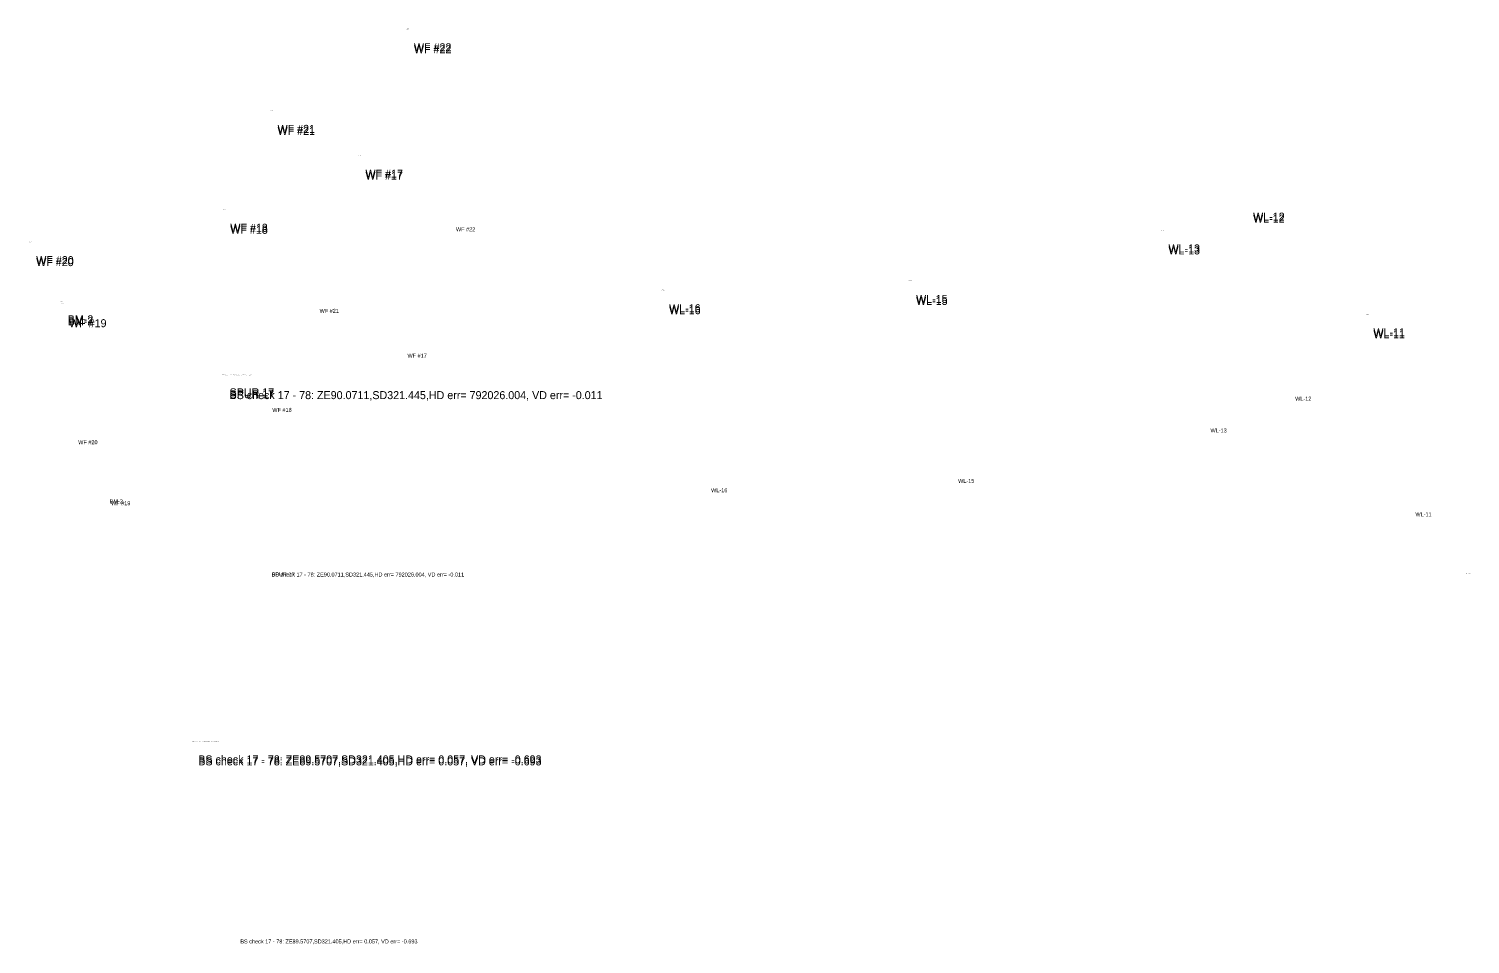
# Model space of a CAD drawing. Extents: x 5447 to 709667, y 4528 to 375472.
# Drawn here: x 705447 to 706023, y 375015 to 375381 of the extents above; entities that cross this region are included whole.
import ezdxf

# ---------------------------------------------------------------- set-up
doc = ezdxf.new("R2010")
doc.units = 0
doc.layers.add('SV_SURVEY_NOTES', color=7, linetype='Continuous')

msp = doc.modelspace()

# ---------------------------------------------------------------- texts
at = {"layer": 'SV_SURVEY_NOTES'}
for s, height, p in [('WF #22', 0.25, (705598.02, 375380.99)), ('WF #22', 3.2, (705600.97, 375372.26)), ('WF #22', 3.2, (705600.97, 375372.26)), ('WF #22', 3.2, (705600.97, 375372.26)), ('WF #22', 3.2, (705600.97, 375372.26)), ('WF #22', 3.2, (705600.97, 375372.26)), ('WF #22', 3.2, (705600.97, 375372.26)), ('WF #22', 3.2, (705600.97, 375372.26)), ('WF #22', 3.2, (705600.97, 375372.26)), ('WF #22', 3.2, (705600.97, 375371.46)), ('WF #22', 3.2, (705600.97, 375371.46)), ('WF #22', 3.2, (705600.97, 375371.46)), ('WF #21', 0.25, (705543.49, 375348.36)), ('WF #21', 3.2, (705546.44, 375339.63)), ('WF #21', 3.2, (705546.44, 375339.63)), ('WF #21', 3.2, (705546.44, 375339.63)), ('WF #21', 3.2, (705546.44, 375339.63)), ('WF #21', 3.2, (705546.44, 375339.63)), ('WF #21', 3.2, (705546.44, 375339.63)), ('WF #21', 3.2, (705546.44, 375339.63)), ('WF #21', 3.2, (705546.44, 375339.63)), ('WF #21', 3.2, (705546.44, 375338.83)), ('WF #21', 3.2, (705546.44, 375338.83)), ('WF #21', 3.2, (705546.44, 375338.83)), ('WF #17', 0.25, (705578.64, 375330.44)), ('WF #17', 3.2, (705581.59, 375321.71)), ('WF #17', 3.2, (705581.59, 375321.71)), ('WF #17', 3.2, (705581.59, 375321.71)), ('WF #17', 3.2, (705581.59, 375321.71)), ('WF #17', 3.2, (705581.59, 375321.71)), ('WF #17', 3.2, (705581.59, 375321.71)), ('WF #17', 3.2, (705581.59, 375321.71)), ('WF #17', 3.2, (705581.59, 375321.71)), ('WF #17', 3.2, (705581.59, 375320.91)), ('WF #17', 3.2, (705581.59, 375320.91)), ('WF #17', 3.2, (705581.59, 375320.91)), ('WL-12', 0.25, (705933.6, 375313.26)), ('WF #18', 0.25, (705524.6, 375308.78)), ('WL-12', 3.2, (705936.55, 375304.53)), ('WL-12', 3.2, (705936.55, 375304.53)), ('WL-12', 3.2, (705936.55, 375304.53)), ('WL-12', 3.2, (705936.55, 375304.53)), ('WL-12', 3.2, (705936.55, 375304.53)), ('WL-12', 3.2, (705936.55, 375304.53)), ('WL-12', 3.2, (705936.55, 375304.53)), ('WL-12', 3.2, (705936.55, 375304.53)), ('WL-12', 3.2, (705936.55, 375303.73)), ('WL-12', 3.2, (705936.55, 375303.73)), ('WL-12', 3.2, (705936.55, 375303.73)), ('WF #18', 3.2, (705527.55, 375300.06)), ('WF #18', 3.2, (705527.55, 375300.06)), ('WF #18', 3.2, (705527.55, 375300.06)), ('WF #18', 3.2, (705527.55, 375300.06)), ('WF #18', 3.2, (705527.55, 375300.06)), ('WF #18', 3.2, (705527.55, 375300.06)), ('WF #18', 3.2, (705527.55, 375300.06)), ('WF #18', 3.2, (705527.55, 375300.06)), ('WF #18', 3.2, (705527.55, 375299.26)), ('WF #18', 3.2, (705527.55, 375299.26)), ('WF #18', 3.2, (705527.55, 375299.26)), ('WF #22', 1.6, (705617.77, 375300.26)), ('WL-13', 0.25, (705899.75, 375300.54)), ('WF #20', 0.25, (705446.98, 375295.85)), ('WL-13', 3.2, (705902.7, 375291.81)), ('WL-13', 3.2, (705902.7, 375291.81)), ('WL-13', 3.2, (705902.7, 375291.81)), ('WL-13', 3.2, (705902.7, 375291.81)), ('WL-13', 3.2, (705902.7, 375291.81)), ('WL-13', 3.2, (705902.7, 375291.81)), ('WL-13', 3.2, (705902.7, 375291.81)), ('WL-13', 3.2, (705902.7, 375291.81)), ('WL-13', 3.2, (705902.7, 375291.01)), ('WL-13', 3.2, (705902.7, 375291.01)), ('WL-13', 3.2, (705902.7, 375291.01)), ('WF #20', 3.2, (705449.93, 375287.12)), ('WF #20', 3.2, (705449.93, 375287.12)), ('WF #20', 3.2, (705449.93, 375287.12)), ('WF #20', 3.2, (705449.93, 375287.12)), ('WF #20', 3.2, (705449.93, 375287.12)), ('WF #20', 3.2, (705449.93, 375287.12)), ('WF #20', 3.2, (705449.93, 375287.12)), ('WF #20', 3.2, (705449.93, 375287.12)), ('WF #20', 3.2, (705449.93, 375286.32)), ('WF #20', 3.2, (705449.93, 375286.32)), ('WF #20', 3.2, (705449.93, 375286.32)), ('WL-16', 0.25, (705700.06, 375276.62)), ('WL-15', 0.25, (705798.83, 375280.35)), ('BM-2', 0.25, (705459.57, 375272.17)), ('WF #19', 0.25, (705460.12, 375271.43)), ('WL-16', 3.2, (705703.01, 375267.89)), ('WL-16', 3.2, (705703.01, 375267.89)), ('WL-16', 3.2, (705703.01, 375267.89)), ('WL-16', 3.2, (705703.01, 375267.89)), ('WL-16', 3.2, (705703.01, 375267.89)), ('WL-16', 3.2, (705703.01, 375267.89)), ('WL-16', 3.2, (705703.01, 375267.89)), ('WL-16', 3.2, (705703.01, 375267.89)), ('WL-16', 3.2, (705703.01, 375267.1)), ('WL-16', 3.2, (705703.01, 375267.1)), ('WL-16', 3.2, (705703.01, 375267.09)), ('WL-15', 3.2, (705801.78, 375271.62)), ('WL-15', 3.2, (705801.78, 375271.62)), ('WL-15', 3.2, (705801.78, 375271.62)), ('WL-15', 3.2, (705801.78, 375271.62)), ('WL-15', 3.2, (705801.78, 375271.62)), ('WL-15', 3.2, (705801.78, 375271.62)), ('WL-15', 3.2, (705801.78, 375271.62)), ('WL-15', 3.2, (705801.78, 375271.62)), ('WL-15', 3.2, (705801.78, 375270.82)), ('WL-15', 3.2, (705801.78, 375270.82)), ('WL-15', 3.2, (705801.78, 375270.82)), ('BM-2', 3.2, (705462.52, 375263.45)), ('BM-2', 3.2, (705462.52, 375263.45)), ('BM-2', 3.2, (705462.52, 375263.45)), ('BM-2', 3.2, (705462.52, 375263.45)), ('BM-2', 3.2, (705462.52, 375263.45)), ('BM-2', 3.2, (705462.52, 375263.45)), ('BM-2', 3.2, (705462.52, 375263.45)), ('BM-2', 3.2, (705462.52, 375263.45)), ('BM-2', 3.2, (705462.52, 375262.65)), ('BM-2', 3.2, (705462.52, 375262.65)), ('BM-2', 3.2, (705462.52, 375262.65)), ('WF #19', 3.2, (705463.07, 375262.7)), ('WF #19', 3.2, (705463.07, 375262.7)), ('WF #19', 3.2, (705463.07, 375262.7)), ('WF #19', 3.2, (705463.07, 375262.7)), ('WF #19', 3.2, (705463.07, 375262.7)), ('WF #19', 3.2, (705463.07, 375262.7)), ('WF #19', 3.2, (705463.07, 375262.7)), ('WF #19', 3.2, (705463.07, 375262.7)), ('WF #19', 3.2, (705463.07, 375261.9)), ('WF #19', 3.2, (705463.07, 375261.9)), ('WF #19', 3.2, (705463.07, 375261.9)), ('WF #21', 1.6, (705563.24, 375267.64)), ('WL-11', 0.25, (705981.7, 375266.97)), ('WL-11', 3.2, (705984.65, 375258.25)), ('WL-11', 3.2, (705984.65, 375258.25)), ('WL-11', 3.2, (705984.65, 375258.25)), ('WL-11', 3.2, (705984.65, 375258.25)), ('WL-11', 3.2, (705984.65, 375258.25)), ('WL-11', 3.2, (705984.65, 375258.25)), ('WL-11', 3.2, (705984.65, 375258.25)), ('WL-11', 3.2, (705984.65, 375258.25)), ('WL-11', 3.2, (705984.65, 375257.45)), ('WL-11', 3.2, (705984.65, 375257.45)), ('WL-11', 3.2, (705984.65, 375257.45)), ('WF #17', 1.6, (705598.39, 375249.71)), ('SPUR 17', 0.25, (705524.31, 375242.99)), ('SPUR 17', 0.25, (705524.31, 375242.99)), ('SPUR 17', 0.25, (705524.31, 375242.99)), ('SPUR 17', 0.25, (705524.31, 375242.99)), ('SPUR 17', 0.25, (705524.31, 375242.99)), ('BS check 17 - 78: ZE90.0711,SD321.445,HD err= 792026.004, VD err= -0.011', 0.25, (705524.31, 375242.64)), ('BS check 17 - 78: ZE90.0711,SD321.445,HD err= 792026.004, VD err= -0.011', 0.25, (705524.31, 375242.64)), ('BS check 17 - 78: ZE90.0711,SD321.445,HD err= 792026.004, VD err= -0.011', 0.25, (705524.31, 375242.64)), ('BS check 17 - 78: ZE90.0711,SD321.445,HD err= 792026.004, VD err= -0.011', 0.25, (705524.31, 375242.64)), ('BS check 17 - 78: ZE90.0711,SD321.445,HD err= 792026.004, VD err= -0.011', 0.25, (705524.31, 375242.64)), ('SPUR 17', 3.2, (705527.26, 375234.26)), ('SPUR 17', 3.2, (705527.26, 375234.26)), ('SPUR 17', 3.2, (705527.26, 375234.26)), ('SPUR 17', 3.2, (705527.26, 375234.26)), ('SPUR 17', 3.2, (705527.26, 375234.26)), ('SPUR 17', 3.2, (705527.26, 375234.26)), ('SPUR 17', 3.2, (705527.26, 375234.26)), ('SPUR 17', 3.2, (705527.26, 375234.26)), ('SPUR 17', 3.2, (705527.26, 375234.26)), ('SPUR 17', 3.2, (705527.26, 375234.26)), ('SPUR 17', 3.2, (705527.26, 375234.26)), ('SPUR 17', 3.2, (705527.26, 375234.26)), ('SPUR 17', 3.2, (705527.26, 375234.26)), ('SPUR 17', 3.2, (705527.26, 375234.26)), ('SPUR 17', 3.2, (705527.26, 375234.26)), ('SPUR 17', 3.2, (705527.26, 375234.26)), ('SPUR 17', 3.2, (705527.26, 375234.26)), ('SPUR 17', 3.2, (705527.26, 375234.26)), ('SPUR 17', 3.2, (705527.26, 375234.26)), ('SPUR 17', 3.2, (705527.26, 375234.26)), ('SPUR 17', 3.2, (705527.26, 375234.26)), ('SPUR 17', 3.2, (705527.26, 375234.26)), ('SPUR 17', 3.2, (705527.26, 375234.26)), ('SPUR 17', 3.2, (705527.26, 375234.26)), ('SPUR 17', 3.2, (705527.26, 375234.26)), ('SPUR 17', 3.2, (705527.26, 375234.26)), ('SPUR 17', 3.2, (705527.26, 375234.26)), ('SPUR 17', 3.2, (705527.26, 375234.26)), ('SPUR 17', 3.2, (705527.26, 375234.26)), ('SPUR 17', 3.2, (705527.26, 375234.26)), ('SPUR 17', 3.2, (705527.26, 375234.26)), ('SPUR 17', 3.2, (705527.26, 375234.26)), ('SPUR 17', 3.2, (705527.26, 375234.26)), ('SPUR 17', 3.2, (705527.26, 375234.26)), ('SPUR 17', 3.2, (705527.26, 375234.26)), ('SPUR 17', 3.2, (705527.26, 375234.26)), ('SPUR 17', 3.2, (705527.26, 375234.26)), ('SPUR 17', 3.2, (705527.26, 375234.26)), ('SPUR 17', 3.2, (705527.26, 375234.26)), ('SPUR 17', 3.2, (705527.26, 375234.26)), ('SPUR 17', 3.2, (705527.26, 375233.46)), ('SPUR 17', 3.2, (705527.26, 375233.46)), ('SPUR 17', 3.2, (705527.26, 375233.46)), ('SPUR 17', 3.2, (705527.26, 375233.46)), ('SPUR 17', 3.2, (705527.26, 375233.46)), ('SPUR 17', 3.2, (705527.26, 375233.46)), ('SPUR 17', 3.2, (705527.26, 375233.46)), ('SPUR 17', 3.2, (705527.26, 375233.46)), ('SPUR 17', 3.2, (705527.26, 375233.46)), ('BS check 17 - 78: ZE90.0711,SD321.445,HD err= 792026.004, VD err= -0.011', 3.2, (705527.26, 375233.94)), ('BS check 17 - 78: ZE90.0711,SD321.445,HD err= 792026.004, VD err= -0.011', 3.2, (705527.26, 375233.94)), ('BS check 17 - 78: ZE90.0711,SD321.445,HD err= 792026.004, VD err= -0.011', 3.2, (705527.26, 375233.94)), ('BS check 17 - 78: ZE90.0711,SD321.445,HD err= 792026.004, VD err= -0.011', 3.2, (705527.26, 375233.94)), ('BS check 17 - 78: ZE90.0711,SD321.445,HD err= 792026.004, VD err= -0.011', 3.2, (705527.26, 375233.94)), ('BS check 17 - 78: ZE90.0711,SD321.445,HD err= 792026.004, VD err= -0.011', 3.2, (705527.26, 375233.94)), ('BS check 17 - 78: ZE90.0711,SD321.445,HD err= 792026.004, VD err= -0.011', 3.2, (705527.26, 375233.94)), ('BS check 17 - 78: ZE90.0711,SD321.445,HD err= 792026.004, VD err= -0.011', 3.2, (705527.26, 375233.94)), ('BS check 17 - 78: ZE90.0711,SD321.445,HD err= 792026.004, VD err= -0.011', 3.2, (705527.26, 375233.94)), ('BS check 17 - 78: ZE90.0711,SD321.445,HD err= 792026.004, VD err= -0.011', 3.2, (705527.26, 375233.94)), ('BS check 17 - 78: ZE90.0711,SD321.445,HD err= 792026.004, VD err= -0.011', 3.2, (705527.26, 375233.94)), ('BS check 17 - 78: ZE90.0711,SD321.445,HD err= 792026.004, VD err= -0.011', 3.2, (705527.26, 375233.94)), ('BS check 17 - 78: ZE90.0711,SD321.445,HD err= 792026.004, VD err= -0.011', 3.2, (705527.26, 375233.94)), ('BS check 17 - 78: ZE90.0711,SD321.445,HD err= 792026.004, VD err= -0.011', 3.2, (705527.26, 375233.94)), ('BS check 17 - 78: ZE90.0711,SD321.445,HD err= 792026.004, VD err= -0.011', 3.2, (705527.26, 375233.94)), ('BS check 17 - 78: ZE90.0711,SD321.445,HD err= 792026.004, VD err= -0.011', 3.2, (705527.26, 375233.94)), ('BS check 17 - 78: ZE90.0711,SD321.445,HD err= 792026.004, VD err= -0.011', 3.2, (705527.26, 375233.94)), ('BS check 17 - 78: ZE90.0711,SD321.445,HD err= 792026.004, VD err= -0.011', 3.2, (705527.26, 375233.94)), ('BS check 17 - 78: ZE90.0711,SD321.445,HD err= 792026.004, VD err= -0.011', 3.2, (705527.26, 375233.94)), ('BS check 17 - 78: ZE90.0711,SD321.445,HD err= 792026.004, VD err= -0.011', 3.2, (705527.26, 375233.94)), ('BS check 17 - 78: ZE90.0711,SD321.445,HD err= 792026.004, VD err= -0.011', 3.2, (705527.26, 375233.94)), ('BS check 17 - 78: ZE90.0711,SD321.445,HD err= 792026.004, VD err= -0.011', 3.2, (705527.26, 375233.94)), ('BS check 17 - 78: ZE90.0711,SD321.445,HD err= 792026.004, VD err= -0.011', 3.2, (705527.26, 375233.94)), ('BS check 17 - 78: ZE90.0711,SD321.445,HD err= 792026.004, VD err= -0.011', 3.2, (705527.26, 375233.94)), ('BS check 17 - 78: ZE90.0711,SD321.445,HD err= 792026.004, VD err= -0.011', 3.2, (705527.26, 375233.94)), ('BS check 17 - 78: ZE90.0711,SD321.445,HD err= 792026.004, VD err= -0.011', 3.2, (705527.26, 375233.94)), ('BS check 17 - 78: ZE90.0711,SD321.445,HD err= 792026.004, VD err= -0.011', 3.2, (705527.26, 375233.94)), ('BS check 17 - 78: ZE90.0711,SD321.445,HD err= 792026.004, VD err= -0.011', 3.2, (705527.26, 375233.94)), ('BS check 17 - 78: ZE90.0711,SD321.445,HD err= 792026.004, VD err= -0.011', 3.2, (705527.26, 375233.94)), ('BS check 17 - 78: ZE90.0711,SD321.445,HD err= 792026.004, VD err= -0.011', 3.2, (705527.26, 375233.94)), ('BS check 17 - 78: ZE90.0711,SD321.445,HD err= 792026.004, VD err= -0.011', 3.2, (705527.26, 375233.94)), ('BS check 17 - 78: ZE90.0711,SD321.445,HD err= 792026.004, VD err= -0.011', 3.2, (705527.26, 375233.94)), ('BS check 17 - 78: ZE90.0711,SD321.445,HD err= 792026.004, VD err= -0.011', 3.2, (705527.26, 375233.94)), ('BS check 17 - 78: ZE90.0711,SD321.445,HD err= 792026.004, VD err= -0.011', 3.2, (705527.26, 375233.94)), ('BS check 17 - 78: ZE90.0711,SD321.445,HD err= 792026.004, VD err= -0.011', 3.2, (705527.26, 375233.94)), ('BS check 17 - 78: ZE90.0711,SD321.445,HD err= 792026.004, VD err= -0.011', 3.2, (705527.26, 375233.94)), ('BS check 17 - 78: ZE90.0711,SD321.445,HD err= 792026.004, VD err= -0.011', 3.2, (705527.26, 375233.94)), ('BS check 17 - 78: ZE90.0711,SD321.445,HD err= 792026.004, VD err= -0.011', 3.2, (705527.26, 375233.94)), ('BS check 17 - 78: ZE90.0711,SD321.445,HD err= 792026.004, VD err= -0.011', 3.2, (705527.26, 375233.94)), ('BS check 17 - 78: ZE90.0711,SD321.445,HD err= 792026.004, VD err= -0.011', 3.2, (705527.26, 375233.94)), ('BS check 17 - 78: ZE90.0711,SD321.445,HD err= 792026.004, VD err= -0.011', 3.2, (705527.26, 375233.14)), ('BS check 17 - 78: ZE90.0711,SD321.445,HD err= 792026.004, VD err= -0.011', 3.2, (705527.26, 375233.14)), ('BS check 17 - 78: ZE90.0711,SD321.445,HD err= 792026.004, VD err= -0.011', 3.2, (705527.26, 375233.14)), ('BS check 17 - 78: ZE90.0711,SD321.445,HD err= 792026.004, VD err= -0.011', 3.2, (705527.26, 375233.14)), ('BS check 17 - 78: ZE90.0711,SD321.445,HD err= 792026.004, VD err= -0.011', 3.2, (705527.26, 375233.14)), ('BS check 17 - 78: ZE90.0711,SD321.445,HD err= 792026.004, VD err= -0.011', 3.2, (705527.26, 375233.14)), ('BS check 17 - 78: ZE90.0711,SD321.445,HD err= 792026.004, VD err= -0.011', 3.2, (705527.26, 375233.14)), ('BS check 17 - 78: ZE90.0711,SD321.445,HD err= 792026.004, VD err= -0.011', 3.2, (705527.26, 375233.14)), ('BS check 17 - 78: ZE90.0711,SD321.445,HD err= 792026.004, VD err= -0.011', 3.2, (705527.26, 375233.14)), ('WL-12', 1.6, (705953.35, 375232.53)), ('WF #18', 1.6, (705544.35, 375228.05)), ('WL-13', 1.6, (705919.5, 375219.81)), ('WF #20', 1.6, (705466.73, 375215.12)), ('WL-15', 1.6, (705818.58, 375199.62)), ('WL-16', 1.6, (705719.81, 375195.89)), ('BM-2', 1.6, (705479.32, 375191.45)), ('WF #19', 1.6, (705479.87, 375190.7)), ('WL-11', 1.6, (706001.45, 375186.25)), ('SPUR 17', 1.6, (705544.06, 375162.26)), ('SPUR 17', 1.6, (705544.06, 375162.26)), ('SPUR 17', 1.6, (705544.06, 375162.26)), ('SPUR 17', 1.6, (705544.06, 375162.26)), ('SPUR 17', 1.6, (705544.06, 375162.26)), ('BS check 17 - 78: ZE90.0711,SD321.445,HD err= 792026.004, VD err= -0.011', 1.6, (705544.06, 375162.18)), ('BS check 17 - 78: ZE90.0711,SD321.445,HD err= 792026.004, VD err= -0.011', 1.6, (705544.06, 375162.18)), ('BS check 17 - 78: ZE90.0711,SD321.445,HD err= 792026.004, VD err= -0.011', 1.6, (705544.06, 375162.18)), ('BS check 17 - 78: ZE90.0711,SD321.445,HD err= 792026.004, VD err= -0.011', 1.6, (705544.06, 375162.18)), ('BS check 17 - 78: ZE90.0711,SD321.445,HD err= 792026.004, VD err= -0.011', 1.6, (705544.06, 375162.18)), ('15IN PINE', 0.25, (706021.78, 375163.39)), ('BS check 17 - 78: ZE89.5707,SD321.405,HD err= 0.057, VD err= -0.693', 0.25, (705511.8, 375096.18)), ('BS check 17 - 78: ZE89.5707,SD321.405,HD err= 0.057, VD err= -0.693', 3.2, (705514.75, 375087.45)), ('BS check 17 - 78: ZE89.5707,SD321.405,HD err= 0.057, VD err= -0.693', 3.2, (705514.75, 375087.45)), ('BS check 17 - 78: ZE89.5707,SD321.405,HD err= 0.057, VD err= -0.693', 3.2, (705514.75, 375087.45)), ('BS check 17 - 78: ZE89.5707,SD321.405,HD err= 0.057, VD err= -0.693', 3.2, (705514.75, 375087.45)), ('BS check 17 - 78: ZE89.5707,SD321.405,HD err= 0.057, VD err= -0.693', 3.2, (705514.75, 375087.45)), ('BS check 17 - 78: ZE89.5707,SD321.405,HD err= 0.057, VD err= -0.693', 3.2, (705514.75, 375087.45)), ('BS check 17 - 78: ZE89.5707,SD321.405,HD err= 0.057, VD err= -0.693', 3.2, (705514.75, 375087.45)), ('BS check 17 - 78: ZE89.5707,SD321.405,HD err= 0.057, VD err= -0.693', 3.2, (705514.75, 375087.45)), ('BS check 17 - 78: ZE89.5707,SD321.405,HD err= 0.057, VD err= -0.693', 3.2, (705514.75, 375086.65)), ('BS check 17 - 78: ZE89.5707,SD321.405,HD err= 0.057, VD err= -0.693', 3.2, (705514.75, 375086.65)), ('BS check 17 - 78: ZE89.5707,SD321.405,HD err= 0.057, VD err= -0.693', 3.2, (705514.75, 375086.65)), ('BS check 17 - 78: ZE89.5707,SD321.405,HD err= 0.057, VD err= -0.693', 1.6, (705531.55, 375015.45))]:
    msp.add_text(s, height=height, dxfattribs=at).set_placement(p)

doc.saveas('drawing.dxf')
